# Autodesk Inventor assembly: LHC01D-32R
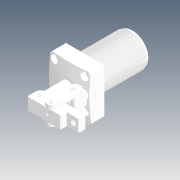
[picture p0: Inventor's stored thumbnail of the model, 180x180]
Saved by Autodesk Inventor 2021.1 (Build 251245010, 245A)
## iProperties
Created: 2019-04
Part Number: LHC01D-32R
Description: STEP AP214
Document SubType Name: Assembly
Designer: user
Title: LHC01D-32R.STEP
Revision Number: ÈÎºÎ
Sending System: SolidWorks 2016
Preprocessor: SwSTEP 2.0
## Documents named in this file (12)
- D:\Vault_2016\Projekty\Clamptek\Hydraulic\LHC01D\Inventor\LHC01D-32R\LHC01D-32R.iam
- D:\Vault_2016\Projekty\Clamptek\Hydraulic\LHC01D\Inventor\LHC01D-32R\LHC01D32»îÈû¸Ë.ipt
- D:\Vault_2016\Projekty\Clamptek\Hydraulic\LHC01D\Inventor\LHC01D-32R\4_2.ipt
- D:\Vault_2016\Projekty\Clamptek\Hydraulic\LHC01D\Inventor\LHC01D-32R\5_2.ipt
- D:\Vault_2016\Projekty\Clamptek\Hydraulic\LHC01D\Inventor\LHC01D-32R\6_2.ipt
- D:\Vault_2016\Projekty\Clamptek\Hydraulic\LHC01D\Inventor\LHC01D-32R\7_2.ipt
- D:\Vault_2016\Projekty\Clamptek\Hydraulic\LHC01D\Inventor\LHC01D-32R\8_2.ipt
- D:\Vault_2016\Projekty\Clamptek\Hydraulic\LHC01D\Inventor\LHC01D-32R\10_2.ipt
- D:\Vault_2016\Projekty\Clamptek\Hydraulic\LHC01D\Inventor\LHC01D-32R\11_2.ipt
- D:\Vault_2016\Projekty\Clamptek\Hydraulic\LHC01D\Inventor\LHC01D-32R\12_2.ipt
- D:\Vault_2016\Projekty\Clamptek\Hydraulic\LHC01D\Inventor\LHC01D-32R\¶ÂÍ·_6.ipt
- D:\Vault_2016\Projekty\Clamptek\Hydraulic\LHC01D\Inventor\LHC01D-32R\LHC01D32R±¾Ìå.ipt
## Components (28 placed, 28 different names)
1. LHC01D32»îÈû¸Ë_1
2. 4_2_2
3. 5_2_3
4. 6_2_4
5. 6_2_5
6. 7_2_6
7. 8_2_7
8. 8_2_8
9. 10_2_9
10. 10_2_10
11. 10_2_11
12. 10_2_12
13. 10_2_13
14. 10_2_14
15. 11_2_15
16. 11_2_16
17. 11_2_17
18. 11_2_18
19. 11_2_19
20. 11_2_20
21. 12_2_21
22. 12_2_22
23. 12_2_23
24. 12_2_24
25. 12_2_25
26. ¶ÂÍ·_6_26
27. ¶ÂÍ·_6_27
28. LHC01D32R±¾Ìå_28
